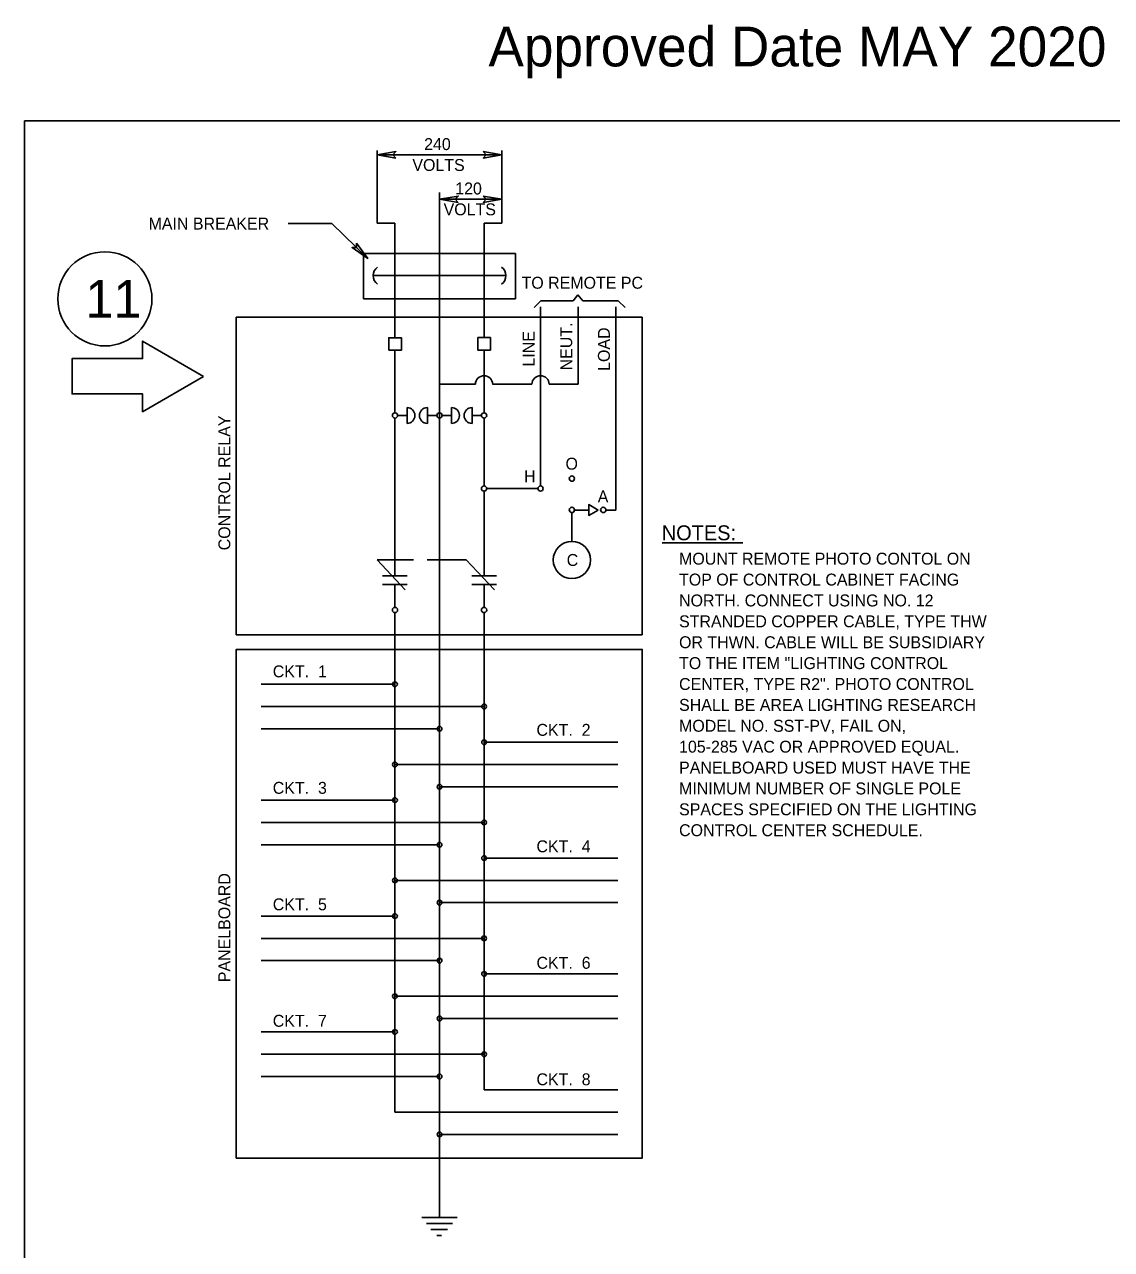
# Model space of a CAD drawing. Extents: x 99992 to 113392, y 99794 to 102182.
# Drawn here: x 110192 to 111285, y 100951 to 102182 of the extents above; entities that cross this region are included whole.
import ezdxf

# ---------------------------------------------------------------- set-up
doc = ezdxf.new("R2010")
doc.units = 0
for name, color, linetype in [('Border Line', 7, 'Continuous'), ('Border Organizer Shape', 7, 'Continuous'), ('Default', 7, 'Continuous'), ('QM Aggregate Gravel', 7, 'Continuous')]:
    doc.layers.add(name, color=color, linetype=linetype)

msp = doc.modelspace()

# ---------------------------------------------------------------- linework, layer by layer
at = {"layer": 'Border Organizer Shape'}
for p, q in [((110546.8, 102055.5), (110546.8, 101982.3)), ((110546.8, 102051.1), (110672.3, 102051.1)), ((110672.3, 102055.5), (110672.3, 101982.3)), ((110609.6, 100982.6), (110609.6, 102013.2)), ((110609.6, 102006.5), (110672.3, 102006.5)), ((110457.4, 101982), (110501.2, 101982)), ((110501.2, 101982), (110537.5, 101947)), ((110546.8, 101982.3), (110564.8, 101982.3)), ((110564.8, 101982.3), (110564.8, 101895.4)), ((110654.4, 101982.3), (110672.3, 101982.3)), ((110654.4, 101982.3), (110654.4, 101895.4)), ((110685.9, 101951.8), (110533.3, 101951.8)), ((110533.3, 101951.8), (110533.3, 101906.2)), ((110685.9, 101906.2), (110685.9, 101951.8)), ((110542.9, 101929.7), (110676.3, 101929.7)), ((110533.3, 101906.2), (110685.9, 101906.2)), ((110704.7, 101897.5), (110711.5, 101904.3)), ((110711.5, 101904.3), (110743.9, 101904.3)), ((110743.9, 101904.3), (110748.8, 101910.5)), ((110753.7, 101904.3), (110748.8, 101910.5)), ((110789.4, 101904.3), (110753.7, 101904.3)), ((110796.2, 101897.5), (110789.4, 101904.3)), ((110813.5, 101888), (110405.2, 101888)), ((110405.2, 101888), (110405.2, 101568.5)), ((110564.8, 101895.4), (110564.8, 101867.4)), ((110654.4, 101895.4), (110654.4, 101867.4)), ((110711.2, 101898.2), (110711.2, 101718.3)), ((110749, 101898.2), (110749, 101820.4)), ((110786.9, 101898.2), (110786.9, 101694)), ((110813.5, 101568.5), (110813.5, 101888)), ((110564.8, 101854.6), (110564.8, 101791.7)), ((110654.4, 101854.8), (110654.4, 101791.7)), ((110609.6, 101820.4), (110645.7, 101820.4)), ((110663, 101820.4), (110702.5, 101820.4)), ((110719.8, 101820.4), (110749, 101820.4)), ((110576.9, 101797), (110576.9, 101781.1)), ((110597.4, 101797), (110597.4, 101781.1)), ((110621.7, 101797), (110621.7, 101781.1)), ((110642.3, 101797), (110642.3, 101781.1)), ((110564.8, 101786.4), (110564.8, 101628)), ((110567.4, 101789.1), (110576.9, 101789.1)), ((110597.4, 101789.1), (110606.9, 101789.1)), ((110612.2, 101789.1), (110621.7, 101789.1)), ((110642.3, 101789.1), (110651.7, 101789.1)), ((110654.4, 101786.4), (110654.4, 101718.3)), ((110657, 101715.6), (110708.5, 101715.6)), ((110654.4, 101712.9), (110654.4, 101628)), ((110742.7, 101691.4), (110742.7, 101662.5)), ((110745.4, 101694), (110759.6, 101694)), ((110776.9, 101694), (110786.9, 101694)), ((110833.5, 101661), (110914.6, 101661)), ((110546.9, 101644.1), (110575.2, 101613.8)), ((110546.9, 101644.1), (110583.3, 101644.1)), ((110597.3, 101644.1), (110636.5, 101644.1)), ((110636.5, 101644.1), (110664.8, 101613.8)), ((110552.4, 101628), (110577.2, 101628)), ((110552.4, 101619.1), (110577.2, 101619.1)), ((110564.8, 101619.1), (110564.8, 101596.1)), ((110642, 101628), (110666.8, 101628)), ((110642, 101619.1), (110666.8, 101619.1)), ((110654.4, 101619.1), (110654.4, 101596.1)), ((110564.8, 101590.8), (110564.8, 101560.7)), ((110654.4, 101590.8), (110654.4, 101560.7)), ((110405.2, 101568.5), (110813.5, 101568.5)), ((110564.8, 101088.7), (110564.8, 101560.7)), ((110654.4, 101111.1), (110654.4, 101560.7)), ((110430.3, 101518.9), (110564.8, 101518.9)), ((110430.3, 101496.5), (110654.4, 101496.5)), ((110430.3, 101474), (110609.6, 101474)), ((110654.4, 101460.6), (110788.8, 101460.6)), ((110564.8, 101438.2), (110788.8, 101438.2)), ((110609.6, 101415.8), (110788.8, 101415.8)), ((110430.3, 101402.4), (110564.8, 101402.4)), ((110430.3, 101379.9), (110654.4, 101379.9)), ((110430.3, 101357.5), (110609.6, 101357.5)), ((110654.4, 101344.1), (110788.8, 101344.1)), ((110564.8, 101321.7), (110788.8, 101321.7)), ((110609.6, 101299.3), (110788.8, 101299.3)), ((110430.3, 101285.8), (110564.8, 101285.8)), ((110430.3, 101263.4), (110654.4, 101263.4)), ((110430.3, 101241), (110609.6, 101241)), ((110654.4, 101227.6), (110788.8, 101227.6)), ((110564.8, 101205.2), (110788.8, 101205.2)), ((110609.6, 101182.8), (110788.8, 101182.8)), ((110430.3, 101169.3), (110564.8, 101169.3)), ((110430.3, 101146.9), (110654.4, 101146.9)), ((110430.3, 101124.5), (110609.6, 101124.5)), ((110654.4, 101111.1), (110788.8, 101111.1)), ((110564.8, 101088.7), (110788.8, 101088.7)), ((110609.6, 101066.3), (110788.8, 101066.3)), ((110591.7, 100982.6), (110627.5, 100982.6)), ((110596.4, 100976.7), (110622.7, 100976.7)), ((110600.9, 100970.7), (110617.7, 100970.7)), ((110606.9, 100964.7), (110611.7, 100964.7))]:
    msp.add_line(p, q, dxfattribs=at)
for points in [[(110565.7, 102047.9), (110546.8, 102051.1), (110565.7, 102054.3), (110562.7, 102051.1)], [(110653.5, 102054.3), (110672.3, 102051.1), (110653.5, 102047.9), (110656.4, 102051.1)], [(110628.4, 102003.3), (110609.6, 102006.5), (110628.4, 102009.7), (110625.4, 102006.5)], [(110653.5, 102009.7), (110672.3, 102006.5), (110653.5, 102003.3), (110656.4, 102006.5)], [(110526.2, 101962.4), (110537.5, 101947), (110521.7, 101957.8), (110526.1, 101958)], [(110558.5, 101854.7), (110571.2, 101854.7), (110571.2, 101867.3), (110558.5, 101867.3)], [(110648.2, 101854.8), (110660.8, 101854.8), (110660.8, 101867.4), (110648.2, 101867.4)], [(110769.1, 101694), (110759.6, 101699.5), (110759.6, 101688.6)], [(110405.2, 101042.5), (110813.5, 101042.5), (110813.5, 101553.9), (110405.2, 101553.9)]]:
    msp.add_lwpolyline(points, close=True, dxfattribs=at)
for centre, radius in [((110564.8, 101789.1), 2.65), ((110609.6, 101789.1), 2.65), ((110654.4, 101789.1), 2.65), ((110742.7, 101725.6), 2.65), ((110654.4, 101715.6), 2.65), ((110711.2, 101715.6), 2.65), ((110742.7, 101694.1), 2.65), ((110774.3, 101694.1), 2.65), ((110742.7, 101643.8), 18.7), ((110564.8, 101593.5), 2.65), ((110654.4, 101593.5), 2.65), ((110564.8, 101518.9), 2.39), ((110654.4, 101496.5), 2.39), ((110609.6, 101474.1), 2.39), ((110654.4, 101460.6), 2.39), ((110564.8, 101438.2), 2.39), ((110609.6, 101415.8), 2.39), ((110564.8, 101402.4), 2.39), ((110654.4, 101379.9), 2.39), ((110609.6, 101357.5), 2.39), ((110654.4, 101344.1), 2.39), ((110564.8, 101321.7), 2.39), ((110609.6, 101299.3), 2.39), ((110564.8, 101285.8), 2.39), ((110654.4, 101263.4), 2.39), ((110609.6, 101241), 2.39), ((110654.4, 101227.6), 2.39), ((110564.8, 101205.2), 2.39), ((110609.6, 101182.8), 2.39), ((110564.8, 101169.3), 2.39), ((110654.4, 101146.9), 2.39), ((110609.6, 101124.5), 2.39), ((110609.6, 101066.3), 2.39)]:
    msp.add_circle(centre, radius, dxfattribs=at)
for centre, radius, start, end in [((110553.7, 101929.7), 10.8, 126.8699, 233.1301), ((110665.5, 101929.7), 10.8, 306.8699, 53.1301), ((110654.4, 101820.4), 8.65, 0, 180), ((110711.2, 101820.4), 8.65, 0, 180), ((110576.9, 101789.1), 7.97, 270, 90), ((110597.4, 101789.1), 7.97, 90, 270), ((110621.7, 101789.1), 7.97, 270, 90), ((110642.3, 101789.1), 7.97, 90, 270)]:
    msp.add_arc(centre, radius, start, end, dxfattribs=at)
at = {"layer": 'Default'}
msp.add_lwpolyline([(110192.2, 102085.3), (113391.9, 102085.3), (113391.9, 99885.7), (110192.2, 99885.7)], close=True, dxfattribs=at)
at = {"layer": 'QM Aggregate Gravel'}
msp.add_lwpolyline([(110372.4, 101828.4), (110311, 101792.9), (110311, 101810.7), (110240, 101810.7), (110240, 101846.2), (110311, 101846.2), (110311, 101863.9)], close=True, dxfattribs=at)
msp.add_circle((110273.1, 101906.3), 47.3, dxfattribs=at)

# ---------------------------------------------------------------- texts
at = {"layer": 'Border Line'}
msp.add_text('Approved Date MAY 2020', height=40, dxfattribs=at).set_placement((110658.8, 102140))
at = {"layer": 'Border Organizer Shape'}
for s, height, p in [('240', 12, (110594.1, 102055.9)), ('VOLTS', 12, (110582.3, 102034.9)), ('120', 12, (110625.4, 102011.3)), ('VOLTS', 12, (110613.7, 101990.3)), ('MAIN BREAKER ', 12, (110317, 101976)), ('TO REMOTE PC', 12, (110692.1, 101916.5)), ('O', 12, (110736.3, 101734.6)), ('H', 12, (110694.6, 101722)), ('A', 12, (110768.7, 101701.7)), ('NOTES:', 15, (110833.1, 101663.6)), ('C', 12, (110737.5, 101637.8)), ('MOUNT REMOTE PHOTO CONTOL ON', 12, (110850.5, 101639.1)), ('TOP OF CONTROL CABINET FACING', 12, (110850.5, 101618.1)), ('NORTH. CONNECT USING NO. 12', 12, (110850.5, 101597.1)), ('STRANDED COPPER CABLE, TYPE THW', 12, (110850.5, 101576.1)), ('OR THWN. CABLE WILL BE SUBSIDIARY', 12, (110850.5, 101555.1)), ('TO THE ITEM "LIGHTING CONTROL', 12, (110850.5, 101534.1)), ('CKT.  1', 12, (110441.9, 101525.8)), ('CENTER, TYPE R2". PHOTO CONTROL', 12, (110850.5, 101513.1)), ('SHALL BE AREA LIGHTING RESEARCH', 12, (110850.5, 101492.1)), ('MODEL NO. SST-PV, FAIL ON,', 12, (110850.5, 101471.1)), ('CKT.  2', 12, (110707.1, 101467)), ('105-285 VAC OR APPROVED EQUAL.', 12, (110850.5, 101450.1)), ('PANELBOARD USED MUST HAVE THE', 12, (110850.5, 101429.1)), ('CKT.  3', 12, (110441.9, 101408.7)), ('MINIMUM NUMBER OF SINGLE POLE', 12, (110850.5, 101408.1)), ('SPACES SPECIFIED ON THE LIGHTING', 12, (110850.5, 101387.1)), ('CONTROL CENTER SCHEDULE. ', 12, (110850.5, 101366.1)), ('CKT.  4', 12, (110707.1, 101349.9)), ('CKT.  5', 12, (110441.9, 101291.6)), ('CKT.  6', 12, (110707.1, 101232.8)), ('CKT.  7', 12, (110441.9, 101174.5)), ('CKT.  8', 12, (110707.1, 101115.7))]:
    msp.add_text(s, height=height, dxfattribs=at).set_placement(p)
for s, p in [('NEUT.', (110743, 101834.4)), ('LOAD', (110780.9, 101833.9)), ('LINE', (110705.2, 101838.2)), ('CONTROL RELAY', (110399.2, 101653.5)), ('PANELBOARD', (110399.2, 101219.3))]:
    msp.add_text(s, height=12, rotation=90, dxfattribs=at).set_placement(p)
at = {"layer": 'QM Aggregate Gravel'}
msp.add_text('11', height=37.84, dxfattribs=at).set_placement((110253.5, 101887.4))

doc.saveas('drawing.dxf')
